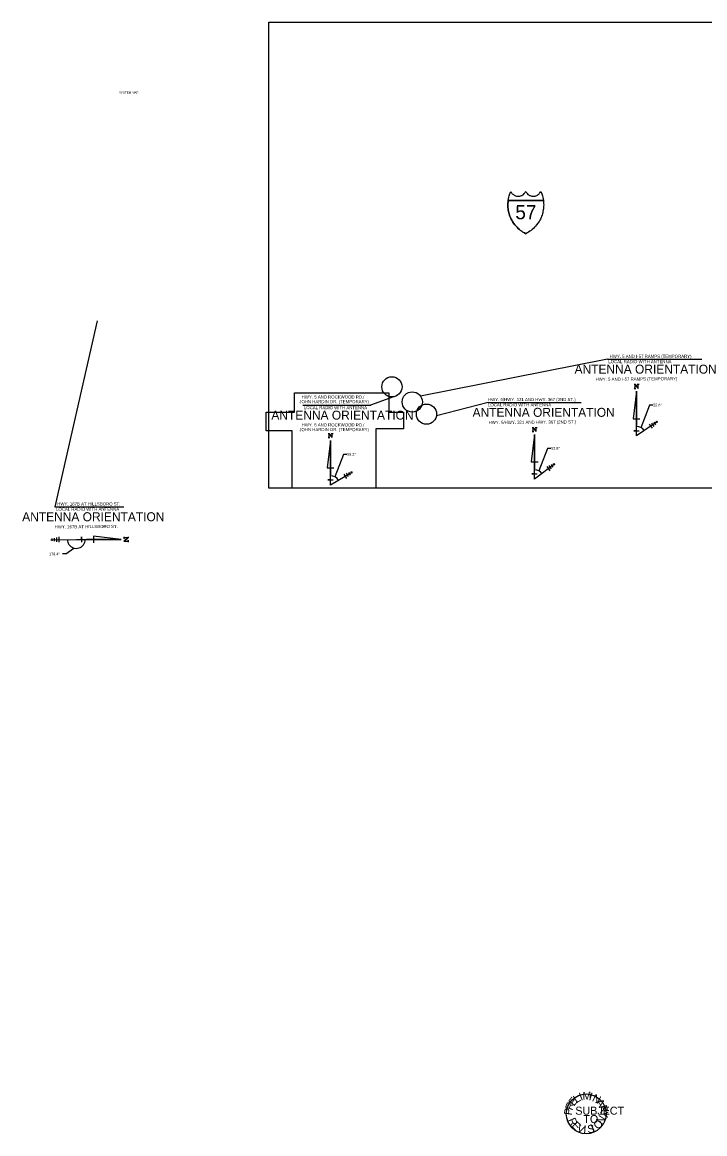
# Model space of a CAD drawing. Extents: x 862297 to 915493, y 1053077 to 1102809.
# Drawn here: x 862297 to 892827, y 1053077 to 1102809 of the extents above; entities that cross this region are included whole.
import ezdxf

# ---------------------------------------------------------------- set-up
doc = ezdxf.new("R2010")
doc.units = 0
for name, color, linetype in [('10', 7, 'Continuous'), ('C-ANNO-NOTE', 7, 'Continuous'), ('G-ANNO-TEXT', 7, 'Continuous'), ('Level 10', 7, 'Continuous'), ('Level 23', 7, 'Continuous'), ('Level 57', 7, 'Continuous'), ('No Plot', 7, 'Continuous'), ('R_Border', 7, 'Continuous'), ('TXT', 7, 'Continuous')]:
    doc.layers.add(name, color=color, linetype=linetype)

msp = doc.modelspace()

# ---------------------------------------------------------------- linework, layer by layer
at = {"layer": '10'}
for p, q in [((865656, 1089452), (863762, 1081128)), ((888469, 1087732), (880111, 1086081)), ((888469, 1087732), (892697, 1087732)), ((874851, 1085674), (877886, 1085674)), ((878897, 1086050), (877871, 1085674)), ((883132, 1085798), (880825, 1085204)), ((883132, 1085798), (887303, 1085798)), ((863762, 1081128), (866848, 1081128))]:
    msp.add_line(p, q, dxfattribs=at)
for centre in [(878833, 1086497), (879744, 1085819), (880379, 1085276)]:
    msp.add_circle(centre, 452, dxfattribs=at)
for centre, start in [((889775, 1084308), 33.6201), ((885212, 1082375), 36.335), ((876086, 1082108), 29.7289)]:
    msp.add_arc(centre, 411, start, 89.7037, dxfattribs=at)
at = {"layer": 'C-ANNO-NOTE'}
for p, q in [((890357, 1085676), (889972, 1084669)), ((890504, 1085676), (890357, 1085676)), ((890640, 1084801), (890559, 1084918)), ((885795, 1083742), (885410, 1082735)), ((885942, 1083742), (885795, 1083742)), ((876668, 1083475), (876283, 1082468)), ((876815, 1083475), (876668, 1083475)), ((886052, 1082909), (885966, 1083022)), ((876981, 1082545), (876908, 1082667)), ((863722, 1079732), (863724, 1079590)), ((864240, 1079020), (864604, 1079285)), ((864240, 1079020), (864093, 1079020))]:
    msp.add_line(p, q, dxfattribs=at)
at = {"layer": 'Level 10'}
for p, q in [((890713, 1084943), (889777, 1084301)), ((890489, 1084644), (890361, 1084831)), ((890560, 1084729), (890458, 1084877)), ((890713, 1084879), (890657, 1084960)), ((877063, 1082682), (876088, 1082100)), ((877059, 1082618), (877008, 1082703)), ((886118, 1083054), (885215, 1082367)), ((885909, 1082745), (885772, 1082925)), ((885976, 1082833), (885867, 1082976)), ((886121, 1082991), (886062, 1083069)), ((876820, 1082398), (876704, 1082592)), ((876897, 1082478), (876805, 1082632)), ((863618, 1079708), (863619, 1079610)), ((863829, 1079748), (863831, 1079568)), ((863935, 1079778), (863937, 1079553)), ((863582, 1079656), (864718, 1079667))]:
    msp.add_line(p, q, dxfattribs=at)
for start, end in [(180.5488, 213.2667), (213.2667, 0.0112)]:
    msp.add_arc((864718, 1079667), 398, start, end, dxfattribs=at)
at = {"layer": 'Level 23'}
msp.add_line((884035, 1094837), (885607, 1094836), dxfattribs=at)
for points in [[(884034, 1094837), (884045, 1094909), (884059, 1094978), (884078, 1095044), (884105, 1095130), (884151, 1095242), (884187, 1095182), (884202, 1095158), (884218, 1095138), (884237, 1095119), (884266, 1095095), (884295, 1095074), (884327, 1095056), (884368, 1095041), (884408, 1095031), (884451, 1095025), (884497, 1095024), (884530, 1095026), (884557, 1095030), (884586, 1095036), (884627, 1095051), (884653, 1095062), (884675, 1095074), (884697, 1095088), (884723, 1095108), (884756, 1095141), (884780, 1095170), (884799, 1095202), (884821, 1095240)], [(884034, 1094837), (884045, 1094909), (884059, 1094978), (884078, 1095044), (884105, 1095130), (884151, 1095242), (884187, 1095182), (884202, 1095158), (884218, 1095138), (884237, 1095119), (884266, 1095095), (884295, 1095074), (884327, 1095056), (884368, 1095041), (884408, 1095031), (884451, 1095025), (884497, 1095024), (884530, 1095026), (884557, 1095030), (884586, 1095036), (884627, 1095051), (884653, 1095062), (884675, 1095074), (884697, 1095088), (884723, 1095108), (884756, 1095141), (884780, 1095170), (884799, 1095202), (884821, 1095240)], [(884821, 1095240), (884843, 1095202), (884862, 1095170), (884886, 1095141), (884920, 1095108), (884945, 1095088), (884967, 1095074), (884989, 1095062), (885015, 1095051), (885056, 1095036), (885085, 1095030), (885112, 1095026), (885145, 1095024), (885191, 1095025), (885234, 1095031), (885274, 1095041), (885315, 1095056), (885347, 1095074), (885376, 1095095), (885405, 1095119), (885424, 1095138), (885440, 1095158), (885455, 1095182), (885491, 1095242), (885537, 1095130), (885564, 1095044), (885583, 1094978), (885598, 1094909), (885609, 1094836)], [(884821, 1095240), (884843, 1095202), (884862, 1095170), (884886, 1095141), (884920, 1095108), (884945, 1095088), (884967, 1095074), (884989, 1095062), (885015, 1095051), (885056, 1095036), (885085, 1095030), (885112, 1095026), (885145, 1095024), (885191, 1095025), (885234, 1095031), (885274, 1095041), (885315, 1095056), (885347, 1095074), (885376, 1095095), (885405, 1095119), (885424, 1095138), (885440, 1095158), (885455, 1095182), (885491, 1095242), (885537, 1095130), (885564, 1095044), (885583, 1094978), (885598, 1094909), (885609, 1094836)], [(884035, 1094837), (884027, 1094772), (884022, 1094704), (884020, 1094642), (884021, 1094585), (884025, 1094519), (884030, 1094463), (884036, 1094421), (884051, 1094341), (884064, 1094285), (884078, 1094234), (884095, 1094181), (884114, 1094129), (884137, 1094071), (884167, 1094005), (884198, 1093946), (884229, 1093893), (884277, 1093818), (884336, 1093739), (884386, 1093680), (884429, 1093634), (884477, 1093587), (884534, 1093536), (884587, 1093493), (884638, 1093456), (884693, 1093419), (884758, 1093380), (884821, 1093347)], [(884821, 1093347), (884758, 1093380), (884693, 1093419), (884638, 1093456), (884587, 1093493), (884534, 1093536), (884477, 1093587), (884429, 1093634), (884386, 1093680), (884336, 1093739), (884277, 1093818), (884229, 1093893), (884198, 1093946), (884167, 1094005), (884137, 1094071), (884114, 1094129), (884095, 1094181), (884078, 1094234), (884064, 1094285), (884051, 1094341), (884036, 1094421), (884030, 1094463), (884025, 1094519), (884021, 1094585), (884020, 1094642), (884022, 1094704), (884027, 1094772), (884035, 1094837)], [(885609, 1094836), (884034, 1094837)], [(885609, 1094836), (884034, 1094837)], [(885607, 1094836), (885615, 1094772), (885620, 1094704), (885622, 1094642), (885621, 1094585), (885618, 1094519), (885612, 1094463), (885606, 1094421), (885591, 1094341), (885578, 1094285), (885564, 1094234), (885547, 1094181), (885529, 1094129), (885505, 1094071), (885475, 1094005), (885444, 1093946), (885413, 1093893), (885365, 1093818), (885306, 1093739), (885257, 1093680), (885213, 1093634), (885166, 1093587), (885108, 1093536), (885055, 1093493), (885004, 1093456), (884949, 1093419), (884884, 1093380), (884821, 1093347)], [(885607, 1094836), (885615, 1094772), (885620, 1094704), (885622, 1094642), (885621, 1094585), (885618, 1094519), (885612, 1094463), (885606, 1094421), (885591, 1094341), (885578, 1094285), (885564, 1094234), (885547, 1094181), (885529, 1094129), (885505, 1094071), (885475, 1094005), (885444, 1093946), (885413, 1093893), (885365, 1093818), (885306, 1093739), (885257, 1093680), (885213, 1093634), (885166, 1093587), (885108, 1093536), (885055, 1093493), (885004, 1093456), (884949, 1093419), (884884, 1093380), (884821, 1093347)]]:
    msp.add_lwpolyline(points, dxfattribs=at)
at = {"layer": 'No Plot'}
for points in [[(899264, 1102809), (899264, 1101818), (905231, 1101818), (905231, 1083636), (893778, 1083636), (893778, 1081963), (873324, 1081963), (873324, 1102809)], [(874475, 1085366), (874475, 1086222), (878697, 1086222), (878697, 1085366), (879352, 1085366), (879352, 1084613), (878111, 1084613), (878111, 1081963), (874374, 1081963), (874374, 1084530), (873207, 1084530), (873207, 1085366)]]:
    msp.add_lwpolyline(points, close=True, dxfattribs=at)
at = {"layer": 'R_Border'}
for p, q in [((889777, 1086301), (889623, 1085070)), ((889777, 1084301), (889777, 1086301)), ((889777, 1086301), (889777, 1084762)), ((889623, 1085070), (889930, 1085070)), ((889777, 1084301), (889777, 1084762)), ((885215, 1084367), (885061, 1083136)), ((885215, 1084367), (885214, 1082828)), ((885215, 1082367), (885215, 1084367)), ((889777, 1084531), (889661, 1084532)), ((889661, 1084532), (889892, 1084532)), ((889777, 1084301), (889777, 1084531)), ((876088, 1084100), (875934, 1082869)), ((876088, 1082100), (876088, 1084100)), ((876088, 1084100), (876088, 1082562)), ((875934, 1082869), (876241, 1082869)), ((885061, 1083136), (885368, 1083136)), ((885215, 1082367), (885214, 1082828)), ((876088, 1082331), (875972, 1082331)), ((875972, 1082331), (876203, 1082331)), ((876088, 1082100), (876088, 1082562)), ((876088, 1082100), (876088, 1082331)), ((885214, 1082598), (885099, 1082598)), ((885099, 1082598), (885330, 1082598)), ((885215, 1082367), (885214, 1082598)), ((864949, 1079667), (864949, 1079782)), ((864949, 1079782), (864949, 1079551)), ((866718, 1079667), (865487, 1079821)), ((865487, 1079821), (865487, 1079513)), ((864718, 1079667), (866718, 1079667)), ((864718, 1079667), (865179, 1079667)), ((864718, 1079667), (864949, 1079667)), ((866718, 1079667), (865179, 1079667))]:
    msp.add_line(p, q, dxfattribs=at)
for points in [[(889664, 1086616), (889710, 1086616), (889853, 1086460)], [(889664, 1086429), (889744, 1086429)], [(889679, 1086615), (889853, 1086429), (889853, 1086584), (889875, 1086615)], [(889700, 1086591), (889700, 1086460), (889679, 1086429)], [(889696, 1086615), (889853, 1086446)], [(889700, 1086460), (889710, 1086429)], [(889715, 1086429), (889700, 1086460), (889720, 1086429)], [(889703, 1086615), (889853, 1086456)], [(889809, 1086615), (889889, 1086616)], [(889831, 1086616), (889853, 1086584), (889863, 1086616)], [(889853, 1086584), (889868, 1086615)], [(885102, 1084682), (885148, 1084682), (885291, 1084527)], [(885116, 1084682), (885291, 1084495), (885291, 1084650), (885313, 1084682)], [(885138, 1084657), (885138, 1084527), (885116, 1084495)], [(885133, 1084682), (885291, 1084512)], [(885141, 1084682), (885291, 1084522)], [(885247, 1084682), (885327, 1084682)], [(885269, 1084682), (885291, 1084650), (885301, 1084682)], [(885291, 1084650), (885305, 1084682)], [(875975, 1084415), (876021, 1084415), (876164, 1084260)], [(875975, 1084228), (876055, 1084228)], [(875990, 1084415), (876164, 1084228), (876164, 1084383), (876186, 1084415)], [(876011, 1084391), (876011, 1084260), (875990, 1084228)], [(876007, 1084415), (876164, 1084245)], [(876011, 1084260), (876021, 1084228)], [(876026, 1084228), (876011, 1084260), (876031, 1084228)], [(876014, 1084415), (876164, 1084255)], [(876120, 1084415), (876200, 1084415)], [(876142, 1084415), (876164, 1084383), (876174, 1084415)], [(876164, 1084383), (876179, 1084415)], [(885102, 1084495), (885182, 1084495)], [(885138, 1084527), (885148, 1084495)], [(885153, 1084495), (885138, 1084527), (885158, 1084495)], [(866846, 1079779), (866846, 1079699)], [(867033, 1079765), (866846, 1079590), (867001, 1079590), (867033, 1079569)], [(867008, 1079743), (866878, 1079743), (866846, 1079765)], [(866878, 1079743), (866846, 1079733)], [(866846, 1079728), (866878, 1079743), (866846, 1079724)], [(867033, 1079748), (866863, 1079590)], [(867033, 1079741), (866873, 1079590)], [(867033, 1079779), (867033, 1079733), (866878, 1079590)], [(867033, 1079612), (867001, 1079590), (867033, 1079581)], [(867001, 1079590), (867033, 1079576)], [(867033, 1079634), (867033, 1079554)]]:
    msp.add_lwpolyline(points, dxfattribs=at)
at = {"layer": 'TXT'}
msp.add_circle((887524, 1053968), 890, dxfattribs=at)

# ---------------------------------------------------------------- texts
at = {"layer": '10'}
for s, rotation, p in [('LOCAL RADIO WITH ANTENNA', 359.9992, (888514, 1087555)), ('HWY. 5 AND I-57 RAMPS (TEMPORARY)', 359.9992, (888572, 1087791)), ('HWY. 5 AND I-57 RAMPS (TEMPORARY)', 0.4159, (887941, 1086765)), ('JOHN HARDIN DR. (TEMPORARY)', 359.9992, (874691, 1085764)), ('HWY. 5 AND ROCKWOOD RD./', 359.9992, (874799, 1085974)), ('HWY. 5/HWY. 321 AND HWY. 367 (2ND ST.)', 359.9992, (883132, 1085857)), ('LOCAL RADIO WITH ANTENNA', 359.9992, (883132, 1085622)), ('LOCAL RADIO WITH ANTENNA', 359.9992, (874895, 1085497)), ('JOHN HARDIN DR. (TEMPORARY)', 359.9992, (874691, 1084513)), ('HWY. 5 AND ROCKWOOD RD./', 359.9992, (874799, 1084723)), ('HWY. 5/HWY. 321 AND HWY. 367 (2ND ST.)', 0.4159, (883157, 1084831)), ('HWY. 167B AT HILLSBORO ST.', 359.9992, (863866, 1081187)), ('LOCAL RADIO WITH ANTENNA', 359.9992, (863808, 1080952)), ('HWY. 167B AT HILLSBORO ST.', 0.4159, (863748, 1080162))]:
    msp.add_text(s, height=140, rotation=rotation, dxfattribs=at).set_placement(p)
at = {"layer": 'G-ANNO-TEXT'}
msp.add_text('SYSTEM MAP', height=96, rotation=360, dxfattribs=at).set_placement((866625, 1099617))
at = {"layer": 'Level 10'}
for s, p in [('55.6%%D', (890519, 1085618)), ('52.8%%D', (885957, 1083684)), ('59.2%%D', (876830, 1083417)), ('179.4%%D', (863499, 1078960))]:
    msp.add_text(s, height=120.2, rotation=359.9988, dxfattribs=at).set_placement(p)
at = {"layer": 'Level 23'}
msp.add_text('57', height=633.5, rotation=359.9988, dxfattribs=at).set_placement((884354, 1093995))
at = {"layer": 'Level 57'}
for p in [(887003, 1087088), (873441, 1085030), (882441, 1085155), (862296, 1080485)]:
    msp.add_text('ANTENNA ORIENTATION', height=400, rotation=359.9992, dxfattribs=at).set_placement(p)
at = {"layer": 'TXT'}
for s, rotation, p in [('I', 22.0105, (887288, 1054551)), ('M', 2.6943, (887366, 1054590)), ('I', 343.3781, (887619, 1054596)), ('N', 333.7199, (887759, 1054553)), ('R', 70.3011, (886903, 1054101)), ('E', 50.9849, (886974, 1054289)), ('L', 31.6687, (887080, 1054433)), ('A', 304.7456, (887927, 1054489)), ('R', 285.4294, (888082, 1054308)), ('P', 82.6089, (886879, 1053892)), ('N', 57.1378, (888232, 1053463)), ('Y', 266.1131, (888165, 1054116)), ('R', 293.7639, (886693, 1053697)), ('E', 314.3262, (886847, 1053416)), ('V', 334.8885, (887069, 1053221)), ('I', 355.4508, (887385, 1053107)), ('S', 5.732, (887592, 1053101)), ('I', 26.2943, (887832, 1053150)), ('O', 36.5754, (888014, 1053249))]:
    msp.add_text(s, height=358, rotation=rotation, dxfattribs=at).set_placement(p)
for s, p in [('SUBJECT', (887037, 1053931)), ('TO', (887398, 1053555))]:
    msp.add_text(s, height=358.1, dxfattribs=at).set_placement(p)

doc.saveas('drawing.dxf')
